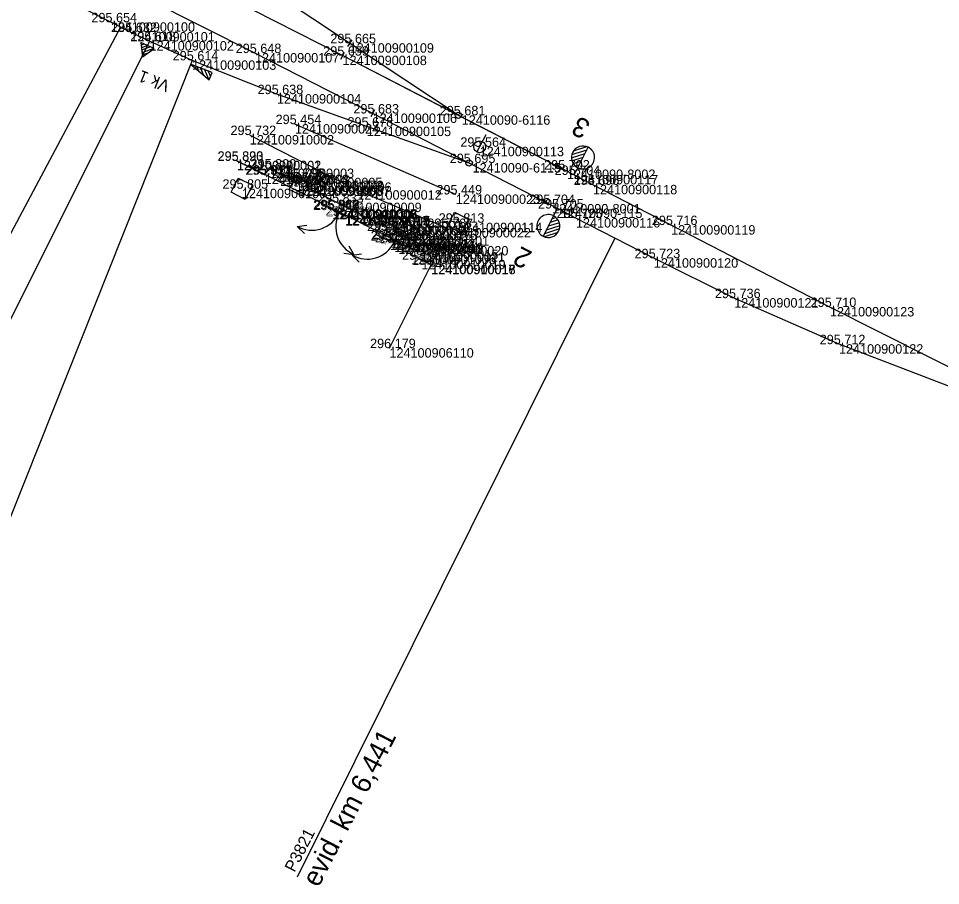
# Model space of a CAD drawing. Extents: x -616949 to -607976, y -1164436 to -1159224.
# Drawn here: x -612906.9 to -612789.7, y -1161814 to -1161703.8 of the extents above; entities that cross this region are included whole.
import ezdxf

# ---------------------------------------------------------------- set-up
doc = ezdxf.new("R2010")
doc.units = 0
for name, color, linetype in [('Vrstva 1', 7, 'Continuous'), ('Vrstva 16', 7, 'Continuous'), ('Vrstva 2', 7, 'Continuous'), ('Vrstva 23', 7, 'Continuous'), ('Vrstva 3', 7, 'Continuous'), ('Vrstva 4', 7, 'Continuous'), ('Vrstva 47', 7, 'Continuous'), ('Vrstva 51', 7, 'Continuous'), ('Vrstva 60', 7, 'Continuous'), ('Vrstva 61', 7, 'Continuous')]:
    doc.layers.add(name, color=color, linetype=linetype)

msp = doc.modelspace()

# ---------------------------------------------------------------- linework, layer by layer
at = {"layer": 'Vrstva 1'}
for points in [[(-612836.3, -1161723.7), (-612837.64, -1161723.01), (-612851, -1161716.12), (-612864.8, -1161706.96), (-612874.11, -1161700.74), (-612883.8, -1161694.67), (-612893.99, -1161688.92), (-612900.94, -1161685.35), (-612902.32, -1161684.67), (-612923.96, -1161673.82), (-612946.7, -1161662.43), (-612968.71, -1161651.4), (-612992.18, -1161639.63), (-613014.55, -1161628.42), (-613038.93, -1161616.22), (-613057.44, -1161606.93), (-613076.92, -1161597.16), (-613100.26, -1161585.47), (-613122.66, -1161574.25), (-613146.78, -1161562.2), (-613166.98, -1161552.11), (-613189.63, -1161540.79)], [(-612836.3, -1161723.7), (-612837.64, -1161723.01), (-612851, -1161716.12), (-612865.7, -1161708.54), (-612879.87, -1161701.29), (-612896.11, -1161693.08), (-612897.16, -1161692.56), (-612899.6, -1161691.36), (-612902.62, -1161689.84), (-612904.01, -1161689.16), (-612926.34, -1161677.97), (-612949.01, -1161666.64), (-612970.85, -1161655.69), (-612994.2, -1161644.02), (-613016.8, -1161632.71), (-613041.11, -1161620.53), (-613059.39, -1161611.38), (-613079.39, -1161601.37), (-613102.4, -1161589.86), (-613124.84, -1161578.63), (-613149.33, -1161566.38), (-613169.01, -1161556.54), (-613191.83, -1161545.12)], [(-612838.4, -1161727.97), (-612839.52, -1161727.39), (-612849.62, -1161722.19), (-612861.87, -1161715.89), (-612876.82, -1161708.21), (-612890.37, -1161701.36), (-612894.8, -1161699.12), (-612896.29, -1161698.37), (-612899.37, -1161696.83), (-612901.81, -1161695.62), (-612928.78, -1161682.13), (-612951.31, -1161670.85), (-612973.15, -1161659.9), (-612996.39, -1161648.28), (-613019.15, -1161636.88), (-613042.98, -1161624.98), (-613061.36, -1161615.73), (-613081.95, -1161605.44), (-613104.41, -1161594.19), (-613127.64, -1161582.55), (-613152.33, -1161570.2), (-613170.83, -1161560.95), (-613193.86, -1161549.42)], [(-612838.4, -1161727.97), (-612839.52, -1161727.39), (-612849.62, -1161722.19), (-612862.62, -1161717.56), (-612874.04, -1161713.43), (-612884.82, -1161709.14), (-612890.21, -1161706.69), (-612892.64, -1161705.54), (-612895.15, -1161704.3), (-612918.74, -1161692.45), (-613021.43, -1161641.02), (-613045.3, -1161629.07), (-613063.44, -1161619.97), (-613084.1, -1161609.63), (-613106.49, -1161598.41), (-613129.98, -1161586.61), (-613154.55, -1161574.23)], [(-612755.44, -1161764.77), (-612756.58, -1161764.2), (-612770.03, -1161757.48), (-612784.45, -1161750.26), (-612803.78, -1161740.48), (-612823.96, -1161730.07), (-612833.89, -1161724.96), (-612836.3, -1161723.7)], [(-612755.44, -1161764.77), (-612756.58, -1161764.2), (-612770.03, -1161757.48), (-612785.18, -1161751.88), (-612802.63, -1161745.21), (-612815.94, -1161739.35), (-612826.15, -1161734.28), (-612836.05, -1161729.18), (-612838.4, -1161727.97)]]:
    msp.add_lwpolyline(points, dxfattribs=at)
at = {"layer": 'Vrstva 16'}
for p, q in [((-612875.58, -1161723.66), (-612879.12, -1161721.89)), ((-612854.41, -1161735.1), (-612856.94, -1161733.84)), ((-612856.94, -1161733.84), (-612856.94, -1161733.84)), ((-612854.45, -1161735.12), (-612854.41, -1161735.1)), ((-612854.45, -1161735.12), (-612854.44, -1161735.13))]:
    msp.add_line(p, q, dxfattribs=at)
for points in [[(-612877.48, -1161718.63), (-612863.81, -1161725.64), (-612852.48, -1161730.44), (-612854.41, -1161735.1)], [(-612879.12, -1161721.89), (-612879.12, -1161721.92), (-612875.58, -1161723.67)], [(-612875.58, -1161723.66), (-612874.94, -1161722.89), (-612871.63, -1161724.56), (-612871.34, -1161724.06), (-612870.18, -1161724.65), (-612870.41, -1161725.19), (-612866.36, -1161727.22), (-612860.59, -1161730.12), (-612860.26, -1161729.54), (-612859.05, -1161730.21), (-612859.31, -1161730.75), (-612857.78, -1161731.5), (-612855.34, -1161732.73), (-612855.78, -1161733.52), (-612856.62, -1161733.21)], [(-612854.45, -1161735.12), (-612855.69, -1161734.48), (-612856.94, -1161733.84)]]:
    msp.add_lwpolyline(points, dxfattribs=at)
at = {"layer": 'Vrstva 2'}
for p, q in [((-612864.52, -1161706.54), (-612865.07, -1161707.37)), ((-612851, -1161716.12), (-612864.8, -1161706.96)), ((-612865.93, -1161708.98), (-612865.47, -1161708.09)), ((-612861.64, -1161715.44), (-612862.1, -1161716.33)), ((-612862.78, -1161718.03), (-612862.45, -1161717.08)), ((-612849.62, -1161722.19), (-612862.62, -1161717.56)), ((-612836.35, -1161720.64), (-612834.66, -1161720.1)), ((-612835.82, -1161722.78), (-612834.48, -1161720.18)), ((-612836.61, -1161721.52), (-612834.89, -1161720.97)), ((-612836.56, -1161721.11), (-612834.64, -1161720.5)), ((-612836.55, -1161721.9), (-612835.14, -1161721.45)), ((-612836.39, -1161722.25), (-612835.38, -1161721.93)), ((-612836.13, -1161722.57), (-612835.63, -1161722.41)), ((-612835.82, -1161722.78), (-612836.3, -1161723.7)), ((-612838.88, -1161728.89), (-612838.4, -1161727.97)), ((-612838.88, -1161728.89), (-612840.22, -1161731.49)), ((-612838.31, -1161729.42), (-612839.31, -1161729.74)), ((-612838.57, -1161729.11), (-612839.07, -1161729.27)), ((-612838.13, -1161730.56), (-612840.05, -1161731.18)), ((-612838.09, -1161730.15), (-612839.81, -1161730.7)), ((-612838.15, -1161729.77), (-612839.56, -1161730.22)), ((-612838.35, -1161731.03), (-612840.03, -1161731.57))]:
    msp.add_line(p, q, dxfattribs=at)
for points in [[(-612836.3, -1161723.7), (-612837.64, -1161723.01), (-612851.06, -1161716.09), (-612865.7, -1161708.54)], [(-612838.4, -1161727.97), (-612839.52, -1161727.39), (-612849.62, -1161722.19), (-612861.87, -1161715.89)], [(-612838.62, -1161722.8), (-612837.64, -1161723.01), (-612838.38, -1161722.34)], [(-612840.5, -1161727.18), (-612839.52, -1161727.39), (-612840.26, -1161726.72)]]:
    msp.add_lwpolyline(points, dxfattribs=at)
for centre in [(-612851, -1161716.12), (-612849.62, -1161722.19)]:
    msp.add_circle(centre, 0.4, dxfattribs=at)
for centre, start, end in [((-612835.15, -1161721.48), 62.7335, 242.6944), ((-612835.14, -1161721.48), 242.4792, 62.9487), ((-612839.55, -1161730.19), 62.5244, 242.9939), ((-612839.55, -1161730.19), 242.7788, 62.7396)]:
    msp.add_arc(centre, 1.46, start, end, dxfattribs=at)
at = {"layer": 'Vrstva 23'}
for p, q in [((-612856.62, -1161733.21), (-612875.58, -1161723.66)), ((-612875.58, -1161723.67), (-612875.58, -1161723.66)), ((-612866.95, -1161728.04), (-612866.98, -1161728.09)), ((-612866.93, -1161728.06), (-612866.96, -1161728.12)), ((-612866.96, -1161728.12), (-612866.86, -1161728.17)), ((-612866.86, -1161728.17), (-612865.4, -1161728.89)), ((-612865.32, -1161728.93), (-612865.4, -1161728.89)), ((-612865.3, -1161728.88), (-612865.32, -1161728.93)), ((-612865.28, -1161728.89), (-612865.3, -1161728.94)), ((-612859.54, -1161731.82), (-612859.66, -1161732.02)), ((-612859.54, -1161731.82), (-612858.5, -1161732.33)), ((-612859.67, -1161732.03), (-612859.66, -1161732.02)), ((-612859.13, -1161732.28), (-612859.67, -1161732.03)), ((-612859.66, -1161732.02), (-612858.6, -1161732.54)), ((-612858.61, -1161732.55), (-612859.13, -1161732.28)), ((-612858.61, -1161732.55), (-612858.6, -1161732.54)), ((-612858.5, -1161732.33), (-612858.6, -1161732.54)), ((-612856.94, -1161733.84), (-612856.62, -1161733.21))]:
    msp.add_line(p, q, dxfattribs=at)
for points in [[(-612870.55, -1161731.14), (-612871.45, -1161730.25), (-612870.24, -1161730.06)], [(-612865.53, -1161733.63), (-612864.28, -1161733.8), (-612864.86, -1161732.73)], [(-612863.6, -1161734.8), (-612864.48, -1161733.9), (-612863.27, -1161733.74)]]:
    msp.add_lwpolyline(points, dxfattribs=at)
for centre, start, end in [((-612869.6, -1161726.89), 241.1532, 334.6731), ((-612862.73, -1161730.29), 152.6037, 246.1236), ((-612862.57, -1161730.57), 240.1264, 333.6463)]:
    msp.add_arc(centre, 3.83, start, end, dxfattribs=at)
at = {"layer": 'Vrstva 3'}
for p, q in [((-612893.9, -1161704.92), (-612940.21, -1161791.8)), ((-612890.21, -1161706.69), (-612933.49, -1161793.23)), ((-612890.88, -1161707.07), (-612891.28, -1161707.21)), ((-612890.48, -1161707.25), (-612891.25, -1161707.54)), ((-612890.09, -1161707.42), (-612891.22, -1161707.85)), ((-612889.69, -1161707.61), (-612891.18, -1161708.17)), ((-612890.45, -1161708.21), (-612891.15, -1161708.48)), ((-612884.82, -1161709.14), (-612918.42, -1161793.57)), ((-612884.71, -1161709.72), (-612884.61, -1161709.94)), ((-612884.22, -1161709.91), (-612883.98, -1161710.47)), ((-612883.73, -1161710.11), (-612883.36, -1161711)), ((-612883.24, -1161710.3), (-612882.72, -1161711.54)), ((-612882.76, -1161710.5), (-612882.47, -1161711.19))]:
    msp.add_line(p, q, dxfattribs=at)
for points in [[(-612891.13, -1161708.71), (-612889.63, -1161707.63), (-612891.31, -1161706.87)], [(-612885.01, -1161709.6), (-612882.63, -1161711.61), (-612882.27, -1161710.69)]]:
    msp.add_lwpolyline(points, close=True, dxfattribs=at)
at = {"layer": 'Vrstva 4'}
for p, q in [((-612892.64, -1161705.54), (-612895.15, -1161704.3)), ((-612851.31, -1161726.18), (-612871.75, -1161717.24)), ((-612823.96, -1161730.07), (-612833.89, -1161724.96)), ((-612826.15, -1161734.28), (-612836.05, -1161729.18)), ((-612831.1, -1161731.73), (-612871.46, -1161812.92))]:
    msp.add_line(p, q, dxfattribs=at)
at = {"layer": 'Vrstva 47'}
msp.add_line((-612848.62, -1161720.79), (-612847.47, -1161718.57), dxfattribs=at)
for points in [[(-612872.49, -1161725.54), (-612871.59, -1161723.75), (-612869.8, -1161724.65), (-612870.7, -1161726.43), (-612872.49, -1161725.54)], [(-612879.83, -1161725.9), (-612878.94, -1161724.11), (-612877.15, -1161725.01), (-612878.05, -1161726.8), (-612879.83, -1161725.9)], [(-612850.59, -1161731.11), (-612852.37, -1161730.2), (-612851.46, -1161728.42), (-612849.68, -1161729.33), (-612850.59, -1161731.11)], [(-612861.46, -1161731.26), (-612860.57, -1161729.47), (-612858.78, -1161730.37), (-612859.68, -1161732.15), (-612861.46, -1161731.26)]]:
    msp.add_lwpolyline(points, dxfattribs=at)
msp.add_circle((-612848.28, -1161720.12), 0.75, dxfattribs=at)
at = {"layer": 'Vrstva 51'}
for p, q in [((-612866.96, -1161728.12), (-612866.98, -1161728.09)), ((-612866.93, -1161728.06), (-612866.95, -1161728.04)), ((-612866.95, -1161728.04), (-612865.28, -1161728.89)), ((-612866.93, -1161728.06), (-612865.3, -1161728.88)), ((-612865.32, -1161728.93), (-612865.3, -1161728.94)), ((-612865.3, -1161728.88), (-612865.28, -1161728.89)), ((-612859.74, -1161745.71), (-612854.44, -1161735.13))]:
    msp.add_line(p, q, dxfattribs=at)
at = {"layer": 'Vrstva 60'}
for p, q in [((-612895.15, -1161704.3), (-612895.15, -1161704.3)), ((-612892.64, -1161705.54), (-612892.64, -1161705.54)), ((-612890.21, -1161706.69), (-612890.21, -1161706.69)), ((-612864.8, -1161706.96), (-612864.8, -1161706.96)), ((-612876.82, -1161708.21), (-612876.82, -1161708.21)), ((-612865.7, -1161708.54), (-612865.7, -1161708.54)), ((-612884.82, -1161709.14), (-612884.82, -1161709.14)), ((-612874.04, -1161713.43), (-612874.04, -1161713.43)), ((-612861.87, -1161715.89), (-612861.87, -1161715.89)), ((-612851, -1161716.12), (-612851, -1161716.12)), ((-612871.75, -1161717.24), (-612871.75, -1161717.24)), ((-612862.62, -1161717.56), (-612862.62, -1161717.56)), ((-612877.48, -1161718.63), (-612877.48, -1161718.63)), ((-612848.28, -1161720.12), (-612848.28, -1161720.12)), ((-612879.12, -1161721.89), (-612879.12, -1161721.89)), ((-612879.12, -1161721.92), (-612879.12, -1161721.92)), ((-612849.62, -1161722.19), (-612849.62, -1161722.19)), ((-612875.58, -1161723.66), (-612875.58, -1161723.66)), ((-612875.58, -1161723.67), (-612875.58, -1161723.67)), ((-612874.94, -1161722.89), (-612874.94, -1161722.89)), ((-612837.64, -1161723.01), (-612837.64, -1161723.01)), ((-612836.3, -1161723.7), (-612836.3, -1161723.7)), ((-612871.63, -1161724.56), (-612871.63, -1161724.56)), ((-612871.34, -1161724.06), (-612871.34, -1161724.06)), ((-612870.18, -1161724.65), (-612870.18, -1161724.65)), ((-612878.49, -1161725.45), (-612878.49, -1161725.45)), ((-612871.15, -1161725.09), (-612871.15, -1161725.09)), ((-612870.41, -1161725.19), (-612870.41, -1161725.19)), ((-612863.81, -1161725.64), (-612863.81, -1161725.64)), ((-612833.89, -1161724.96), (-612833.89, -1161724.96)), ((-612866.36, -1161727.22), (-612866.36, -1161727.22)), ((-612851.31, -1161726.18), (-612851.31, -1161726.18)), ((-612866.98, -1161728.09), (-612866.98, -1161728.09)), ((-612866.96, -1161728.12), (-612866.96, -1161728.12)), ((-612866.95, -1161728.04), (-612866.95, -1161728.04)), ((-612866.93, -1161728.06), (-612866.93, -1161728.06)), ((-612866.86, -1161728.17), (-612866.86, -1161728.17)), ((-612839.52, -1161727.39), (-612839.52, -1161727.39)), ((-612838.4, -1161727.97), (-612838.4, -1161727.97)), ((-612865.4, -1161728.89), (-612865.4, -1161728.89)), ((-612865.32, -1161728.93), (-612865.32, -1161728.93)), ((-612865.3, -1161728.88), (-612865.3, -1161728.88)), ((-612865.3, -1161728.94), (-612865.3, -1161728.94)), ((-612865.28, -1161728.89), (-612865.28, -1161728.89)), ((-612860.26, -1161729.54), (-612860.26, -1161729.54)), ((-612836.05, -1161729.18), (-612836.05, -1161729.18)), ((-612860.59, -1161730.12), (-612860.59, -1161730.12)), ((-612859.31, -1161730.75), (-612859.31, -1161730.75)), ((-612859.05, -1161730.21), (-612859.05, -1161730.21)), ((-612852.48, -1161730.44), (-612852.48, -1161730.44)), ((-612851.03, -1161729.77), (-612851.03, -1161729.77)), ((-612823.96, -1161730.07), (-612823.96, -1161730.07)), ((-612860.12, -1161730.81), (-612860.12, -1161730.81)), ((-612859.54, -1161731.82), (-612859.54, -1161731.82)), ((-612857.78, -1161731.5), (-612857.78, -1161731.5)), ((-612859.67, -1161732.03), (-612859.67, -1161732.03)), ((-612859.66, -1161732.02), (-612859.66, -1161732.02)), ((-612859.13, -1161732.28), (-612859.13, -1161732.28)), ((-612858.61, -1161732.55), (-612858.61, -1161732.55)), ((-612858.6, -1161732.54), (-612858.6, -1161732.54)), ((-612858.5, -1161732.33), (-612858.5, -1161732.33)), ((-612855.34, -1161732.73), (-612855.34, -1161732.73)), ((-612856.94, -1161733.84), (-612856.94, -1161733.84)), ((-612856.94, -1161733.84), (-612856.94, -1161733.84)), ((-612856.62, -1161733.21), (-612856.62, -1161733.21)), ((-612855.78, -1161733.52), (-612855.78, -1161733.52)), ((-612826.15, -1161734.28), (-612826.15, -1161734.28)), ((-612855.69, -1161734.48), (-612855.69, -1161734.48)), ((-612854.45, -1161735.12), (-612854.45, -1161735.12)), ((-612854.44, -1161735.13), (-612854.44, -1161735.13)), ((-612854.41, -1161735.1), (-612854.41, -1161735.1)), ((-612815.94, -1161739.35), (-612815.94, -1161739.35)), ((-612803.78, -1161740.48), (-612803.78, -1161740.48)), ((-612859.74, -1161745.71), (-612859.74, -1161745.71)), ((-612802.63, -1161745.21), (-612802.63, -1161745.21))]:
    msp.add_line(p, q, dxfattribs=at)

# ---------------------------------------------------------------- texts
at = {"layer": 'Vrstva 2'}
for s, rotation, p in [('3', 152.7139, (-612834.04, -1161717.01)), ('2', 152.7592, (-612841.46, -1161733.54))]:
    msp.add_text(s, height=2.5, rotation=rotation, dxfattribs=at).set_placement(p)
at = {"layer": 'Vrstva 3'}
msp.add_text('Vk 1', height=1.5, rotation=158.3031, dxfattribs=at).set_placement((-612887.51, -1161711.83))
at = {"layer": 'Vrstva 4'}
for s, height, p in [('evid. km 6,441', 2.5, (-612868.75, -1161814.34)), ('P3821', 1.5, (-612871.8, -1161812.4))]:
    msp.add_text(s, height=height, rotation=62.7698, dxfattribs=at).set_placement(p)
at = {"layer": 'Vrstva 60'}
for s, p in [('124100900100', (-612895.15, -1161705.5)), ('124100900101', (-612892.64, -1161706.74)), ('124100900102', (-612890.21, -1161707.89)), ('124100900109', (-612864.8, -1161708.16)), ('124100900107', (-612876.82, -1161709.41)), ('124100900108', (-612865.7, -1161709.74)), ('124100900103', (-612884.82, -1161710.34)), ('124100900104', (-612874.04, -1161714.63)), ('124100900106', (-612861.87, -1161717.09)), (' 12410090-6116', (-612851, -1161717.32)), ('124100900024', (-612871.75, -1161718.44)), ('124100900105', (-612862.62, -1161718.76)), ('124100910002', (-612877.48, -1161719.83)), ('124100900113', (-612848.28, -1161721.32)), ('124100900002', (-612879.12, -1161723.09)), ('124100900001', (-612879.12, -1161723.12)), (' 12410090-6115', (-612849.62, -1161723.39)), ('124100910003', (-612875.58, -1161724.87)), ('124100900004', (-612875.58, -1161724.86)), ('124100900003', (-612874.94, -1161724.09)), (' 12410090-8002', (-612837.64, -1161724.21)), ('124100900117', (-612836.3, -1161724.9)), ('124100910004', (-612871.63, -1161725.76)), ('124100900005', (-612871.34, -1161725.26)), ('124100900006', (-612870.18, -1161725.85)), ('124100900118', (-612833.89, -1161726.16)), ('124100906100', (-612878.49, -1161726.65)), ('124100900008', (-612871.15, -1161726.29)), ('124100910007', (-612870.41, -1161726.39)), ('124100900012', (-612863.81, -1161726.84)), ('124100900009', (-612866.36, -1161728.42)), ('124100900023', (-612851.31, -1161727.38)), ('124100901010', (-612866.98, -1161729.29)), ('124100901009', (-612866.96, -1161729.32)), ('124100910008', (-612866.95, -1161729.24)), ('124100900007', (-612866.93, -1161729.27)), ('124100910006', (-612866.86, -1161729.36)), (' 12410090-8001', (-612839.52, -1161728.59)), (' 12410090-115', (-612838.4, -1161729.17)), ('124100910011', (-612865.4, -1161730.09)), ('124100901007', (-612865.32, -1161730.13)), ('124100900010', (-612865.3, -1161730.08)), ('124100901008', (-612865.3, -1161730.14)), ('124100900011', (-612865.28, -1161730.09)), ('124100910014', (-612860.26, -1161730.74)), ('124100900116', (-612836.05, -1161730.38)), ('124100900013', (-612860.59, -1161731.32)), ('124100900017', (-612860.12, -1161732.01)), ('124100900016', (-612859.31, -1161731.95)), ('124100910015', (-612859.05, -1161731.41)), ('124100900022', (-612852.48, -1161731.64)), ('124100900114', (-612851.03, -1161730.97)), ('124100900119', (-612823.96, -1161731.28)), ('124100910012', (-612859.54, -1161733.02)), ('124100906101', (-612857.78, -1161732.7)), ('124100901004', (-612859.67, -1161733.23)), ('124100901003', (-612859.66, -1161733.22)), ('124100900014', (-612859.13, -1161733.48)), ('124100901001', (-612858.61, -1161733.75)), ('124100901002', (-612858.6, -1161733.74)), ('124100900019', (-612858.5, -1161733.53)), ('124100900020', (-612855.34, -1161733.93)), ('124100901005', (-612856.94, -1161735.04)), ('124100901006', (-612856.94, -1161735.04)), ('124100900015', (-612856.62, -1161734.41)), ('124100900021', (-612855.78, -1161734.72)), ('124100900120', (-612826.15, -1161735.48)), ('124100910019', (-612855.69, -1161735.68)), ('124100910017', (-612854.45, -1161736.32)), ('124100910016', (-612854.44, -1161736.33)), ('124100900018', (-612854.41, -1161736.3)), ('124100900121', (-612815.94, -1161740.55)), ('124100900123', (-612803.78, -1161741.68)), ('124100906110', (-612859.74, -1161746.91)), ('124100900122', (-612802.63, -1161746.41))]:
    msp.add_text(s, height=1.2, dxfattribs=at).set_placement(p)
at = {"layer": 'Vrstva 61'}
for s, p in [('295.654', (-612897.6, -1161704.3)), ('295.632', (-612895.09, -1161705.54)), ('295.618', (-612892.67, -1161706.69)), ('295.665', (-612867.25, -1161706.96)), ('295.648', (-612879.27, -1161708.21)), ('295.659', (-612868.15, -1161708.54)), ('295.614', (-612887.27, -1161709.14)), ('295.638', (-612876.49, -1161713.43)), ('295.683', (-612864.32, -1161715.89)), ('295.681', (-612853.35, -1161716.12)), ('295.454', (-612874.2, -1161717.24)), ('295.678', (-612865.07, -1161717.56)), ('295.732', (-612879.93, -1161718.63)), ('295.564', (-612850.73, -1161720.12)), ('295.823', (-612881.57, -1161721.89)), ('295.890', (-612881.57, -1161721.92)), ('295.695', (-612852.08, -1161722.19)), ('295.973', (-612878.03, -1161723.67)), ('295.811', (-612877.93, -1161723.66)), ('295.800', (-612877.39, -1161722.89)), ('295.702', (-612840.09, -1161723.01)), ('295.704', (-612838.75, -1161723.7)), ('295.795', (-612874.08, -1161724.56)), ('295.798', (-612873.79, -1161724.06)), ('295.798', (-612872.63, -1161724.65)), ('295.696', (-612836.34, -1161724.96)), ('295.805', (-612880.95, -1161725.45)), ('295.796', (-612873.6, -1161725.09)), ('295.804', (-612872.86, -1161725.19)), ('295.773', (-612866.26, -1161725.64)), ('295.833', (-612868.81, -1161727.22)), ('295.449', (-612853.77, -1161726.18)), ('295.867', (-612869.43, -1161728.09)), ('295.865', (-612869.41, -1161728.04)), ('295.942', (-612869.41, -1161728.12)), ('295.940', (-612869.38, -1161728.06)), ('295.943', (-612869.32, -1161728.17)), ('295.704', (-612841.97, -1161727.39)), ('295.705', (-612840.86, -1161727.97)), ('295.949', (-612867.85, -1161728.89)), ('295.948', (-612867.78, -1161728.93)), ('295.859', (-612867.76, -1161728.94)), ('295.953', (-612867.75, -1161728.88)), ('295.864', (-612867.73, -1161728.89)), ('295.812', (-612862.71, -1161729.54)), ('295.725', (-612838.5, -1161729.18)), ('295.811', (-612862.95, -1161730.12)), ('295.836', (-612862.57, -1161730.81)), ('295.783', (-612861.76, -1161730.75)), ('295.751', (-612861.41, -1161730.21)), ('295.767', (-612854.93, -1161730.44)), ('295.813', (-612853.48, -1161729.77)), ('295.716', (-612826.41, -1161730.07)), ('295.855', (-612862, -1161731.82)), ('295.768', (-612860.24, -1161731.5)), ('295.839', (-612862.12, -1161732.02)), ('295.976', (-612862.12, -1161732.03)), ('295.975', (-612861.59, -1161732.28)), ('295.975', (-612861.06, -1161732.55)), ('295.838', (-612861.05, -1161732.54)), ('295.852', (-612860.94, -1161732.33)), ('295.803', (-612857.79, -1161732.73)), ('295.904', (-612859.39, -1161733.84)), ('295.973', (-612859.39, -1161733.84)), ('295.844', (-612859.07, -1161733.21)), ('295.865', (-612858.23, -1161733.52)), ('295.723', (-612828.6, -1161734.28)), ('295.976', (-612858.14, -1161734.48)), ('295.979', (-612856.91, -1161735.12)), ('295.930', (-612856.86, -1161735.1)), ('296.091', (-612856.79, -1161735.13)), ('295.736', (-612818.39, -1161739.35)), ('295.710', (-612806.23, -1161740.48)), ('296.179', (-612862.2, -1161745.71)), ('295.712', (-612805.08, -1161745.21))]:
    msp.add_text(s, height=1.2, dxfattribs=at).set_placement(p)

doc.saveas('drawing.dxf')
